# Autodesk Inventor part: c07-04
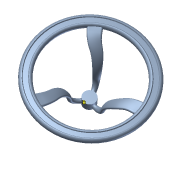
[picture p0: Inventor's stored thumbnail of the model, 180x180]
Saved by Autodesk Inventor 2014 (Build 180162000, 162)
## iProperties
Created: 2010-12
Part Number: c07-04
Document SubType Name: Modeling
Designer: Thom Tremblay
Density: 1 g/cm^3
Material: Generic
Appearance: Light Steel Blue
Author: Thom Tremblay
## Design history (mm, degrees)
sketch "Sketch2"
  geometry: L1 (0, 0)-(-11.43, 0); L2 (-11.43, 0)-(-11.43, 16.51); L3 (-11.43, 16.51)-(0, 16.51); L4 (0, 16.51)-(0, 0); L5 (-96.52, 66.04)-(-86.36, 66.04); L6 (-86.36, 76.2)-(-96.52, 76.2); L7 (-95.25, 74.93)-(-87.63, 74.93); L8 (-96.52, 76.2)-(-95.25, 74.93); L9 (-86.36, 76.2)-(-87.63, 74.93); A1 r 5.08 centre (-86.36, 71.12) between (-86.36, 66.04) and (-86.36, 76.2); A2 r 5.08 centre (-96.52, 71.12) between (-96.52, 76.2) and (-96.52, 66.04)
  constraints: 18 end point, 4 parallel, 4 point on circle, 4 tangent, 2 centre point, 2 horizontal, 2 perpendicular
  dimensions: "d6" = 16.51 distance of L1.end L2.end; "d7" = 22.86 diameter of L2 L4; "d10" = 5.08 radius of A1; "d11" = 20.32 dimension on A2 A1; "d12" = 3.81 distance from line of A1.centre L7; "d13" = 7.62 distance of L7.start L7.end; "d14" = 76.2 distance from line of L6.end L1; "d15" = 203.2 dimension on A2 L4
revolve "Revolution1" sketch "Sketch2" stored, may be unused: angle "d16" = 120 deg
sketch "Plane Sketch 1"
  geometry: L1 (-48.26, -83.589)-(-43.18, -74.79) reference; L2 (-48.26, 83.589)-(-43.18, 74.79) reference; L3 (0, 0)-(-85.598, 31.155); L4 (0, 0)-(-86.36, 0); A1 r 86.36 centre (0, 0) between (-43.18, 74.79) and (-43.18, -74.79) reference; A2 r 96.52 centre (0, 0) between (-48.26, 83.589) and (-48.26, -83.589) reference; 1 further point
  constraints: 4 end point, 1 point on circle
  dimensions: "d65" = 20 deg angle of L3 L4; "d66" = 91.09202 distance of L3.start L3.end
workplane "Work Plane2"
sketch "Sketch10"
  geometry: L1 (-8.89, 5.08)-(8.89, 5.08); L2 (-8.89, 2.54)-(8.89, 2.54); L3 (8.89, 7.62)-(-8.89, 7.62); A1 r 2.54 centre (-8.89, 5.08) between (-8.89, 7.62) and (-8.89, 2.54); A2 r 2.54 centre (8.89, 5.08) between (8.89, 2.54) and (8.89, 7.62); 2 further points
  constraints: 8 end point, 4 point on circle, 4 tangent, 2 centre point, 1 midpoint, 1 parallel, 1 vertical alignment
  dimensions: "d67" = 71.12 distance from line of L1 point (0, -66.04); "d68" = 17.78 distance of L3.start L3.end; "d69" = 2.54 radius of A2
sketch "Loft Sketch 1"
  node "Project from Sketch10"
sketch "Loft Sketch 2"
  geometry: C1 r 3.81 at (0, 7.62); 1 further point
  constraints: 1 centre point, 1 vertical alignment
  dimensions: "d63" = 7.62 diameter of C1; "d64" = 7.62 distance of point (0, 0) C1.centre
sketch "3D Sketch3"
  node "Project from Loft Sketch 2"
sketch "Rail Sketch 1"
  geometry: L1 (11.43, 0)-(-6.921, 0); L2 (76.378, 27.799)-(69.218, 25.193); L3 (0, 0)-(5.715, -9.899) reference; L4 (5.715, 9.899)-(0, 0) reference; A1 r 50.8 centre (86.592, -22.543) between (69.218, 25.193) and (53.126, 15.675); A2 r 63.293 centre (11.43, 63.293) between (11.43, 0) and (53.126, 15.675); A3 r 11.43 centre (0, 0) between (5.715, -9.899) and (5.715, 9.899) reference
  constraints: 4 end point, 4 point on circle, 3 tangent, 2 centre point, 1 horizontal
  dimensions: "d73" = 50.8 radius of A1; "d75" = 7.62 distance of L2.start L2.end; "d76" = 20 deg angle of L2 L1 (= d65)
sketch "Rail Sketch 2"
  geometry: L1 (-76.378, 71.12)-(-95.236, 71.12); L2 (-76.378, 71.12)-(-69.018, 69.148); L3 (-11.43, 7.62)-(5.882, 7.62); L4 (-11.43, 16.51)-(-11.43, 0) reference; A1 r 17.78 centre (-11.43, 25.4) between (-29.076, 23.224) and (-11.43, 7.62); A2 r 54.441 centre (-83.108, 16.562) between (-29.076, 23.224) and (-69.018, 69.148); 1 further point
  constraints: 6 end point, 4 point on circle, 3 tangent, 2 centre point, 1 horizontal, 1 perpendicular
  dimensions: "d78" = 15 deg angle of L2 L1; "d79" = 7.62 distance of L1.start L2.end; "d80" = 17.78 radius of A1
sketch "3D Sketch4"
loft "Loft2" sketch "3D Sketch4" dims "d81" = 0, "d82" = 90 deg, "d83" = 0, "d84" = 90 deg, "d85" = 0, "d86" = 90 deg
pattern_circular "Circular Pattern2" dims "d88" = 360 deg
body "Solid1"
node "3D Intersection2"
